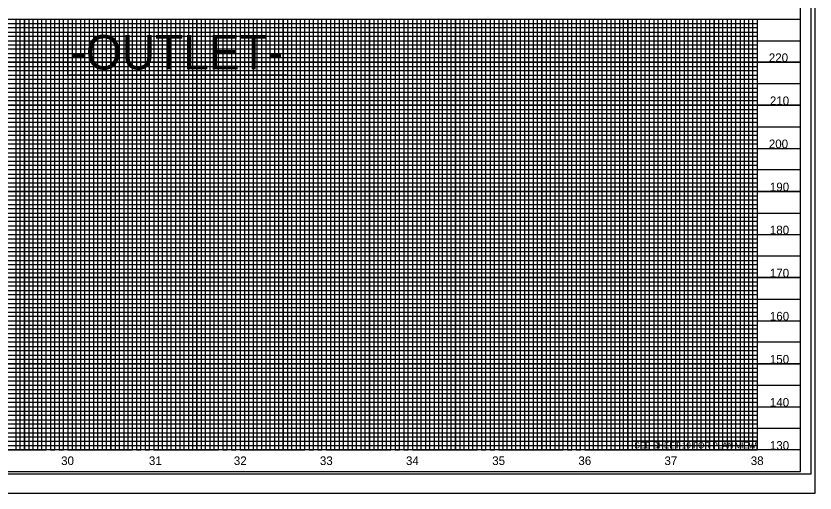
# Model space of a CAD drawing. Extents: x 1779926 to 1781610, y 602514 to 621564.
# Drawn here: x 1780683 to 1781610, y 602514 to 603068 of the extents above; entities that cross this region are included whole.
import ezdxf

# ---------------------------------------------------------------- set-up
doc = ezdxf.new("R2010")
doc.units = 0
for name, color, linetype in [('Exist Vertical Profile Horizontal Axis Label Major', 7, 'Continuous'), ('Exist Vertical Profile Vertical Axis Label', 7, 'Continuous'), ('Prop DSN Text', 7, 'Continuous'), ('Prop Grid Mask', 7, 'Continuous'), ('Scratch_Level_0', 7, 'Continuous'), ('Sheet DOT Grid CELL', 7, 'Continuous'), ('Sheet Layout Profile Border Port 2', 7, 'Continuous'), ('Sheet Plot Border Inside CELL', 7, 'Continuous'), ('Sheet Plot Border Outside CELL', 7, 'Continuous'), ('Sheet Profile CELL', 7, 'Continuous'), ('Sheet Profile Grid Major CELL', 7, 'Continuous'), ('Sheet Profile Grid Middle CELL', 7, 'Continuous'), ('Sheet Profile Grid Minor CELL', 7, 'Continuous')]:
    doc.layers.add(name, color=color, linetype=linetype)

msp = doc.modelspace()

# ---------------------------------------------------------------- linework, layer by layer
at = {"layer": 'Prop Grid Mask'}
for points in [[(1780742.96, 603049.45), (1780997.96, 603049.45), (1780997.96, 602999.45), (1780742.96, 602999.45)], [(1781542.96, 602574.45), (1781397.96, 602574.45), (1781397.96, 602564.45), (1781542.96, 602564.45)]]:
    msp.add_lwpolyline(points, close=True, dxfattribs=at)
at = {"layer": 'Scratch_Level_0'}
msp.add_lwpolyline([(1780142.96, 602564.45), (1780142.96, 603064.45), (1781542.96, 603064.45), (1781542.96, 602564.45)], close=True, dxfattribs=at)
at = {"layer": 'Sheet DOT Grid CELL'}
for p, q in [((1780092.96, 603064.45), (1781592.85, 603064.45)), ((1780692.96, 603064.45), (1780692.96, 602564.45)), ((1780742.96, 603064.45), (1780742.96, 602564.45)), ((1780792.96, 603064.45), (1780792.96, 602564.45)), ((1780842.96, 603064.45), (1780842.96, 602564.45)), ((1780892.96, 603064.45), (1780892.96, 602564.45)), ((1780942.96, 603064.45), (1780942.96, 602564.45)), ((1780992.96, 603064.45), (1780992.96, 602564.45)), ((1781042.96, 603064.45), (1781042.96, 602564.45)), ((1781092.96, 603064.45), (1781092.96, 602564.45)), ((1781142.96, 603064.45), (1781142.96, 602564.45)), ((1781192.96, 603064.45), (1781192.96, 602564.45)), ((1781242.96, 603064.45), (1781242.96, 602564.45)), ((1781292.96, 603064.45), (1781292.96, 602564.45)), ((1781342.96, 603064.45), (1781342.96, 602564.45)), ((1781392.96, 603064.45), (1781392.96, 602564.45)), ((1781442.96, 603064.45), (1781442.96, 602564.45)), ((1781492.96, 603064.45), (1781492.96, 602564.45)), ((1781542.96, 603064.45), (1781542.96, 602564.45)), ((1780092.96, 603014.45), (1781592.85, 603014.45)), ((1780092.96, 602964.45), (1781592.85, 602964.45)), ((1780092.96, 602914.45), (1781592.85, 602914.45)), ((1780092.96, 602864.45), (1781592.85, 602864.45)), ((1780092.96, 602814.45), (1781592.85, 602814.45)), ((1780092.96, 602764.45), (1781592.85, 602764.45)), ((1780092.96, 602714.45), (1781592.85, 602714.45)), ((1780092.96, 602664.45), (1781592.85, 602664.45)), ((1780092.96, 602614.45), (1781592.85, 602614.45))]:
    msp.add_line(p, q, dxfattribs=at)
at = {"layer": 'Sheet Layout Profile Border Port 2'}
msp.add_lwpolyline([(1780142.96, 603064.45), (1781542.96, 603064.45), (1781542.96, 602564.45), (1780142.96, 602564.45)], close=True, dxfattribs=at)
msp.add_lwpolyline([(1780142.96, 603064.45), (1781542.96, 603064.45), (1781542.96, 602564.45), (1780142.96, 602564.45)], close=True, dxfattribs=at)
at = {"layer": 'Sheet Plot Border Inside CELL'}
msp.add_lwpolyline([(1779938.96, 602536.9), (1781605.46, 602536.9), (1781605.46, 603592), (1779938.96, 603592)], close=True, dxfattribs=at)
at = {"layer": 'Sheet Plot Border Outside CELL'}
msp.add_lwpolyline([(1779925.96, 602514.45), (1781609.96, 602514.45), (1781609.96, 603614.45), (1779925.96, 603614.45)], close=True, dxfattribs=at)
at = {"layer": 'Sheet Profile CELL'}
for p, q in [((1780092.96, 603064.45), (1781592.96, 603064.45)), ((1781592.96, 602564.45), (1780092.96, 602564.45)), ((1780092.96, 602539.45), (1781592.96, 602539.45))]:
    msp.add_line(p, q, dxfattribs=at)
msp.add_lwpolyline([(1781592.96, 603589.45), (1780092.96, 603589.45), (1780092.96, 602539.45), (1781592.96, 602539.45)], close=True, dxfattribs=at)
at = {"layer": 'Sheet Profile Grid Major CELL'}
for p, q in [((1780692.96, 603064.45), (1780742.96, 603064.45)), ((1780792.96, 603064.45), (1780842.96, 603064.45)), ((1780892.96, 603064.45), (1780942.96, 603064.45)), ((1780992.96, 603064.45), (1781042.96, 603064.45)), ((1781092.96, 603064.45), (1781142.96, 603064.45)), ((1781192.96, 603064.45), (1781242.96, 603064.45)), ((1781292.96, 603064.45), (1781342.96, 603064.45)), ((1781392.96, 603064.45), (1781442.96, 603064.45)), ((1781492.96, 603064.45), (1781542.96, 603064.45)), ((1781492.96, 602564.45), (1781492.96, 602564.45))]:
    msp.add_line(p, q, dxfattribs=at)
for points in [[(1780642.96, 602564.45), (1780692.96, 602564.45), (1780692.96, 603064.45), (1780742.96, 603064.45), (1780742.96, 602564.45), (1780792.96, 602564.45), (1780792.96, 603064.45), (1780842.96, 603064.45), (1780842.96, 602564.45), (1780892.96, 602564.45), (1780892.96, 603064.45), (1780942.96, 603064.45), (1780942.96, 602564.45), (1780992.96, 602564.45), (1780992.96, 603064.45), (1781042.96, 603064.45), (1781042.96, 602564.45), (1781092.96, 602564.45), (1781092.96, 603064.45), (1781142.96, 603064.45), (1781142.96, 602564.45), (1781192.96, 602564.45), (1781192.96, 603064.45), (1781242.96, 603064.45), (1781242.96, 602564.45), (1781292.96, 602564.45), (1781292.96, 603064.45), (1781342.96, 603064.45), (1781342.96, 602564.45), (1781392.96, 602564.45), (1781392.96, 603064.45), (1781442.96, 603064.45), (1781442.96, 602564.45), (1781492.96, 602564.45), (1781492.96, 602564.45), (1781492.96, 603064.45), (1781542.96, 603064.45), (1781542.96, 602564.45)], [(1781592.96, 603014.45), (1780092.96, 603014.45)], [(1781592.96, 602964.45), (1780092.96, 602964.45), (1780092.96, 602914.45), (1781592.96, 602914.45)], [(1781592.96, 602864.45), (1780092.96, 602864.45), (1780092.96, 602814.45), (1781592.96, 602814.45)], [(1781592.96, 602764.45), (1780092.96, 602764.45), (1780092.96, 602714.45), (1781592.96, 602714.45)], [(1781592.96, 602664.45), (1780092.96, 602664.45), (1780092.96, 602664.45), (1780092.96, 602614.45), (1781592.96, 602614.45)], [(1781592.96, 602564.45), (1780092.96, 602564.45)]]:
    msp.add_lwpolyline(points, dxfattribs=at)
at = {"layer": 'Sheet Profile Grid Middle CELL'}
for points in [[(1780667.96, 602564.45), (1780717.96, 602564.45), (1780717.96, 602564.45), (1780717.96, 603064.45), (1780767.96, 603064.45), (1780767.96, 602564.45), (1780817.96, 602564.45), (1780817.96, 603064.45), (1780867.96, 603064.45), (1780867.96, 602564.45), (1780917.96, 602564.45), (1780917.96, 603064.45), (1780967.96, 603064.45), (1780967.96, 602564.45), (1781017.96, 602564.45), (1781017.96, 603064.45), (1781067.96, 603064.45), (1781067.96, 602564.45), (1781117.96, 602564.45), (1781117.96, 603064.45), (1781167.96, 603064.45), (1781167.96, 602564.45), (1781217.96, 602564.45), (1781217.96, 603064.45), (1781267.96, 603064.45), (1781267.96, 602564.45), (1781317.96, 602564.45), (1781317.96, 603064.45), (1781367.96, 603064.45), (1781367.96, 602564.45), (1781417.96, 602564.45), (1781417.96, 603064.45), (1781467.96, 603064.45), (1781467.96, 602564.45), (1781517.96, 602564.45), (1781517.96, 603064.45)], [(1780092.96, 603039.45), (1781592.96, 603039.45)], [(1781592.96, 602989.45), (1780092.96, 602989.45), (1780092.96, 602939.45), (1781592.96, 602939.45)], [(1781592.96, 602889.45), (1780092.96, 602889.45), (1780092.96, 602839.45), (1781592.96, 602839.45)], [(1781592.96, 602789.45), (1780092.96, 602789.45), (1780092.96, 602739.45), (1781592.96, 602739.45)], [(1781592.96, 602689.45), (1780092.96, 602689.45), (1780092.96, 602639.45), (1781592.96, 602639.45)], [(1781592.96, 602589.45), (1780092.96, 602589.45)]]:
    msp.add_lwpolyline(points, dxfattribs=at)
at = {"layer": 'Sheet Profile Grid Minor CELL'}
for p, q in [((1780142.96, 603059.45), (1781542.96, 603059.45)), ((1781542.96, 603054.45), (1780142.96, 603054.45)), ((1780142.96, 603049.45), (1781542.96, 603049.45)), ((1781542.96, 603044.45), (1780142.96, 603044.45)), ((1780142.96, 603034.45), (1781542.96, 603034.45)), ((1781542.96, 603029.45), (1780142.96, 603029.45)), ((1780142.96, 603024.45), (1781542.96, 603024.45)), ((1781542.96, 603019.45), (1780142.96, 603019.45)), ((1780142.96, 603009.45), (1781542.96, 603009.45)), ((1781542.96, 603004.45), (1780142.96, 603004.45)), ((1780142.96, 602999.45), (1781542.96, 602999.45)), ((1781542.96, 602994.45), (1780142.96, 602994.45)), ((1780142.96, 602984.45), (1781542.96, 602984.45)), ((1781542.96, 602979.45), (1780142.96, 602979.45)), ((1780142.96, 602974.45), (1781542.96, 602974.45)), ((1781542.96, 602969.45), (1780142.96, 602969.45)), ((1780142.96, 602959.45), (1781542.96, 602959.45)), ((1781542.96, 602954.45), (1780142.96, 602954.45)), ((1780142.96, 602949.45), (1781542.96, 602949.45)), ((1781542.96, 602944.45), (1780142.96, 602944.45)), ((1780142.96, 602934.45), (1781542.96, 602934.45)), ((1781542.96, 602929.45), (1780142.96, 602929.45)), ((1780142.96, 602924.45), (1781542.96, 602924.45)), ((1781542.96, 602919.45), (1780142.96, 602919.45)), ((1780142.96, 602909.45), (1781542.96, 602909.45)), ((1781542.96, 602904.45), (1780142.96, 602904.45)), ((1780142.96, 602899.45), (1781542.96, 602899.45)), ((1781542.96, 602894.45), (1780142.96, 602894.45)), ((1780142.96, 602884.45), (1781542.96, 602884.45)), ((1781542.96, 602879.45), (1780142.96, 602879.45)), ((1780142.96, 602874.45), (1781542.96, 602874.45)), ((1781542.96, 602869.45), (1780142.96, 602869.6)), ((1780142.96, 602859.45), (1781542.96, 602859.45)), ((1781542.96, 602854.45), (1780142.96, 602854.45)), ((1780142.96, 602849.45), (1781542.96, 602849.45)), ((1781542.96, 602844.45), (1780142.96, 602844.45)), ((1780142.96, 602834.45), (1781542.96, 602834.45)), ((1781542.96, 602829.45), (1780142.96, 602829.45)), ((1780142.96, 602824.45), (1781542.96, 602824.45)), ((1781542.96, 602819.45), (1780142.96, 602819.45)), ((1780142.96, 602809.45), (1781542.96, 602809.45)), ((1781542.96, 602804.45), (1780142.96, 602804.45)), ((1780142.96, 602799.45), (1781542.96, 602799.45)), ((1781542.96, 602794.45), (1780142.96, 602794.45)), ((1780142.96, 602784.45), (1781542.96, 602784.45)), ((1781542.96, 602779.45), (1780142.96, 602779.45)), ((1780142.96, 602774.45), (1781542.96, 602774.45)), ((1781542.96, 602769.45), (1780142.96, 602769.45)), ((1780142.96, 602759.45), (1781542.96, 602759.45)), ((1781542.96, 602754.45), (1780142.96, 602754.45)), ((1780142.96, 602749.45), (1781542.96, 602749.45)), ((1781542.96, 602744.45), (1780142.96, 602744.45)), ((1780142.96, 602734.45), (1781542.96, 602734.45)), ((1781542.96, 602729.45), (1780142.96, 602729.45)), ((1780142.96, 602724.45), (1781542.96, 602724.45)), ((1781542.96, 602719.45), (1780142.96, 602719.45)), ((1780142.96, 602709.45), (1781542.96, 602709.45)), ((1781542.96, 602704.45), (1780142.96, 602704.45)), ((1780142.96, 602699.45), (1781542.96, 602699.45)), ((1781542.96, 602694.45), (1780142.96, 602694.45)), ((1780142.96, 602684.45), (1781542.96, 602684.45)), ((1781542.96, 602679.45), (1780142.96, 602679.45)), ((1780142.96, 602674.45), (1781542.96, 602674.45)), ((1781542.96, 602669.45), (1780142.96, 602669.45)), ((1780142.96, 602659.45), (1781542.96, 602659.45)), ((1781542.96, 602654.45), (1780142.96, 602654.45)), ((1780142.96, 602649.45), (1781542.96, 602649.45)), ((1781542.96, 602644.45), (1780142.96, 602644.45)), ((1780142.96, 602634.45), (1781542.96, 602634.45)), ((1781542.96, 602629.45), (1780142.96, 602629.45)), ((1780142.96, 602624.45), (1781542.96, 602624.45)), ((1781542.96, 602619.45), (1780142.96, 602619.45)), ((1780142.96, 602609.45), (1781542.96, 602609.45)), ((1781542.96, 602604.45), (1780142.96, 602604.45)), ((1780142.96, 602599.45), (1781542.96, 602599.45)), ((1781542.96, 602594.45), (1780142.96, 602594.45)), ((1780142.96, 602584.45), (1781542.96, 602584.45)), ((1781542.96, 602579.45), (1780142.96, 602579.45)), ((1780142.96, 602574.45), (1781542.96, 602574.45)), ((1780142.96, 602569.45), (1781542.96, 602569.45)), ((1781542.96, 602569.45), (1781542.96, 602569.45))]:
    msp.add_line(p, q, dxfattribs=at)
for points in [[(1780677.96, 603064.45), (1780682.96, 603064.45), (1780682.96, 602564.45), (1780687.96, 602564.45), (1780687.96, 603064.45), (1780697.96, 603064.45), (1780697.96, 602564.45), (1780702.96, 602564.45), (1780702.96, 603064.45), (1780707.96, 603064.45), (1780707.96, 602564.45), (1780712.96, 602564.45), (1780712.96, 603064.45), (1780722.96, 603064.45), (1780722.96, 602564.45), (1780727.96, 602564.45), (1780727.96, 603064.45), (1780732.96, 603064.45), (1780732.96, 602564.45), (1780737.96, 602564.45), (1780737.96, 603064.45), (1780747.96, 603064.45), (1780747.96, 602564.45), (1780752.96, 602564.45), (1780752.96, 603064.45), (1780757.96, 603064.45), (1780757.96, 602564.45), (1780762.96, 602564.45), (1780762.96, 603064.45), (1780772.96, 603064.45), (1780772.96, 602564.45), (1780777.96, 602564.45), (1780777.96, 603064.45), (1780782.96, 603064.45), (1780782.96, 602564.45), (1780787.96, 602564.45), (1780787.96, 603064.45), (1780797.96, 603064.45), (1780797.96, 602564.45), (1780797.96, 602564.45), (1780802.96, 602564.45), (1780802.96, 603064.45), (1780807.96, 603064.45), (1780807.96, 602564.45), (1780812.96, 602564.45), (1780812.96, 603064.45), (1780822.96, 603064.45), (1780822.96, 602564.45), (1780827.96, 602564.45), (1780827.96, 603064.45), (1780832.96, 603064.45), (1780832.96, 602564.45), (1780837.96, 602564.45), (1780837.96, 603064.45), (1780847.96, 603064.45), (1780847.96, 602564.45), (1780852.96, 602564.45), (1780852.96, 603064.45), (1780857.96, 603064.45), (1780857.96, 602564.45), (1780862.96, 602564.45), (1780862.96, 603064.45), (1780872.96, 603064.45), (1780872.96, 602564.45), (1780877.96, 602564.45), (1780877.96, 603064.45), (1780882.96, 603064.45), (1780882.96, 602564.45), (1780887.96, 602564.45), (1780887.96, 603064.45), (1780897.96, 603064.45), (1780897.96, 602564.45), (1780902.96, 602564.45), (1780902.96, 603064.45), (1780907.96, 603064.45), (1780907.96, 602564.45), (1780912.96, 602564.45), (1780912.96, 603064.45), (1780922.96, 603064.45), (1780922.96, 602564.45), (1780927.96, 602564.45), (1780927.96, 603064.45), (1780932.96, 603064.45), (1780932.96, 602564.45), (1780937.96, 602564.45), (1780937.96, 603064.45), (1780947.96, 603064.45), (1780947.96, 602564.45), (1780952.66, 602565), (1780952.96, 602564.45), (1780952.96, 603064.45), (1780957.96, 603064.45), (1780957.96, 602564.45), (1780962.96, 602564.45), (1780962.96, 603064.45), (1780972.96, 603064.45), (1780972.96, 602564.45), (1780977.96, 602564.45)], [(1780977.96, 602564.45), (1780977.96, 603064.45), (1780982.96, 603064.45), (1780982.96, 602564.45), (1780987.96, 602564.45), (1780987.96, 603064.45), (1780997.96, 603064.45), (1780997.96, 602564.45), (1781002.96, 602564.45), (1781002.96, 603064.45), (1781007.96, 603064.45), (1781007.96, 602564.45), (1781012.96, 602564.45), (1781012.96, 603064.45), (1781022.96, 603064.45), (1781022.96, 602564.45), (1781027.96, 602564.45), (1781027.96, 603064.45), (1781032.96, 603064.45), (1781032.96, 602564.45), (1781037.96, 602564.45), (1781037.96, 603064.45), (1781047.96, 603064.45), (1781047.96, 602564.45), (1781052.96, 602564.45), (1781052.96, 603064.45), (1781057.96, 603064.45), (1781057.96, 602564.45), (1781062.96, 602564.45), (1781062.96, 603064.45), (1781072.96, 603064.45), (1781072.96, 602564.45), (1781077.96, 602564.45), (1781077.96, 603064.45), (1781082.96, 603064.45), (1781082.96, 602564.45), (1781087.96, 602564.45), (1781087.96, 603064.45), (1781097.96, 603064.45), (1781097.96, 602564.45), (1781102.96, 602564.45), (1781102.96, 603064.45), (1781107.96, 603064.45), (1781107.96, 602564.45), (1781112.96, 602564.45), (1781112.96, 603064.45), (1781122.96, 603064.45), (1781122.96, 602564.45), (1781127.96, 602564.45), (1781127.96, 603064.45), (1781132.96, 603064.45), (1781132.96, 602564.45), (1781137.96, 602564.45), (1781137.96, 603064.45), (1781147.96, 603064.45), (1781147.96, 602564.45), (1781152.96, 602564.45), (1781152.96, 603064.45), (1781157.96, 603064.45), (1781157.96, 602564.45), (1781162.96, 602564.45), (1781162.96, 603064.45), (1781172.96, 603064.45), (1781172.96, 602564.45), (1781177.96, 602564.45), (1781177.96, 603064.45), (1781182.96, 603064.45), (1781182.96, 602564.45), (1781187.96, 602564.45), (1781187.96, 603064.45), (1781197.96, 603064.45), (1781197.96, 602564.45), (1781202.96, 602564.45), (1781202.96, 603064.45), (1781207.96, 603064.45), (1781207.96, 602564.45), (1781212.96, 602564.45), (1781212.96, 603064.45), (1781222.96, 603064.45), (1781222.96, 602564.45), (1781227.96, 602564.45), (1781227.96, 603064.45), (1781232.96, 603064.45), (1781232.96, 602564.45), (1781237.96, 602564.45), (1781237.96, 603064.45), (1781247.96, 603064.45), (1781247.96, 602564.45), (1781252.96, 602564.45), (1781252.96, 603064.45), (1781257.96, 603064.45), (1781257.96, 602564.45), (1781262.96, 602564.45), (1781262.96, 603064.45), (1781272.96, 603064.45), (1781272.96, 602564.45), (1781277.96, 602564.45), (1781277.96, 603064.45), (1781282.96, 603064.45), (1781282.96, 602564.45)], [(1781282.96, 602564.45), (1781287.96, 602564.45), (1781287.96, 603064.45), (1781297.96, 603064.45), (1781297.96, 602564.45), (1781302.96, 602564.45), (1781302.96, 603064.45), (1781307.96, 603064.45), (1781307.96, 602564.45), (1781312.96, 602564.45), (1781312.96, 603064.45), (1781322.96, 603064.45), (1781322.96, 602564.45), (1781327.96, 602564.45), (1781327.96, 603064.45), (1781332.96, 603064.45), (1781332.96, 602564.45), (1781337.96, 602564.45), (1781337.96, 603064.45), (1781347.96, 603064.45), (1781347.96, 602564.45), (1781352.96, 602564.45), (1781352.96, 603064.45), (1781357.96, 603064.45), (1781357.96, 602564.45), (1781362.96, 602564.45), (1781362.96, 603064.45), (1781372.96, 603064.45), (1781372.96, 602564.45), (1781377.96, 602564.45), (1781377.96, 603064.45), (1781382.96, 603064.45), (1781382.96, 602564.45), (1781387.96, 602564.45), (1781387.96, 603064.45), (1781397.96, 603064.45), (1781397.96, 602564.45), (1781402.96, 602564.45), (1781402.96, 603064.45), (1781407.96, 603064.45), (1781407.96, 602564.45), (1781412.96, 602564.45), (1781412.96, 603064.45), (1781422.96, 603064.45), (1781422.96, 602564.45), (1781427.96, 602564.45), (1781427.96, 603064.45), (1781432.96, 603064.45), (1781432.96, 602564.45), (1781437.96, 602564.45), (1781437.96, 603064.45), (1781447.96, 603064.45), (1781447.96, 602564.45), (1781452.96, 602564.45), (1781452.96, 603064.45), (1781457.96, 603064.45), (1781457.96, 602564.45), (1781462.96, 602564.45), (1781462.96, 603064.45), (1781472.96, 603064.45), (1781472.96, 602564.45), (1781477.96, 602564.45), (1781477.96, 603064.45), (1781482.96, 603064.45), (1781482.96, 602564.45), (1781487.96, 602564.45), (1781487.96, 603064.45), (1781497.96, 603064.45), (1781497.96, 602564.45), (1781502.96, 602564.45), (1781502.96, 603064.45), (1781507.96, 603064.45), (1781507.96, 602564.45), (1781512.96, 602564.45), (1781512.96, 603064.45), (1781522.96, 603064.45), (1781522.96, 602564.45), (1781527.96, 602564.45), (1781527.96, 603064.45), (1781532.96, 603064.45), (1781532.96, 602564.45), (1781537.96, 602564.45), (1781537.96, 603064.45), (1781542.96, 603064.45)]]:
    msp.add_lwpolyline(points, dxfattribs=at)

# ---------------------------------------------------------------- texts
at = {"layer": 'Exist Vertical Profile Horizontal Axis Label Major'}
for s, p in [('30', (1780735.35, 602546.95)), ('31', (1780837.19, 602546.95)), ('32', (1780935.73, 602546.95)), ('33', (1781035.57, 602546.95)), ('34', (1781135.41, 602546.95)), ('35', (1781235.5, 602546.95)), ('36', (1781335.44, 602546.95)), ('37', (1781435.3, 602546.95)), ('38', (1781535.43, 602546.95))]:
    msp.add_text(s, height=10, dxfattribs=at).set_placement(p)
at = {"layer": 'Exist Vertical Profile Vertical Axis Label'}
for s, height, p in [('-OUTLET-', 40, (1780746.27, 603006.04)), ('220', 10, (1781556.39, 603014.7)), ('210', 10, (1781557.59, 602964.7)), ('200', 10, (1781556.39, 602914.7)), ('190', 10, (1781557.59, 602864.7)), ('180', 10, (1781557.59, 602814.7)), ('170', 10, (1781557.59, 602764.7)), ('160', 10, (1781557.59, 602714.7)), ('150', 10, (1781557.59, 602664.7)), ('140', 10, (1781557.59, 602614.7)), ('130', 10, (1781557.59, 602564.7))]:
    msp.add_text(s, height=height, dxfattribs=at).set_placement(p)
at = {"layer": 'Prop DSN Text'}
msp.add_text('SEE SHEET 10 FOR PLAN VIEW', height=7, dxfattribs=at).set_placement((1781400.35, 602566.4))

doc.saveas('drawing.dxf')
